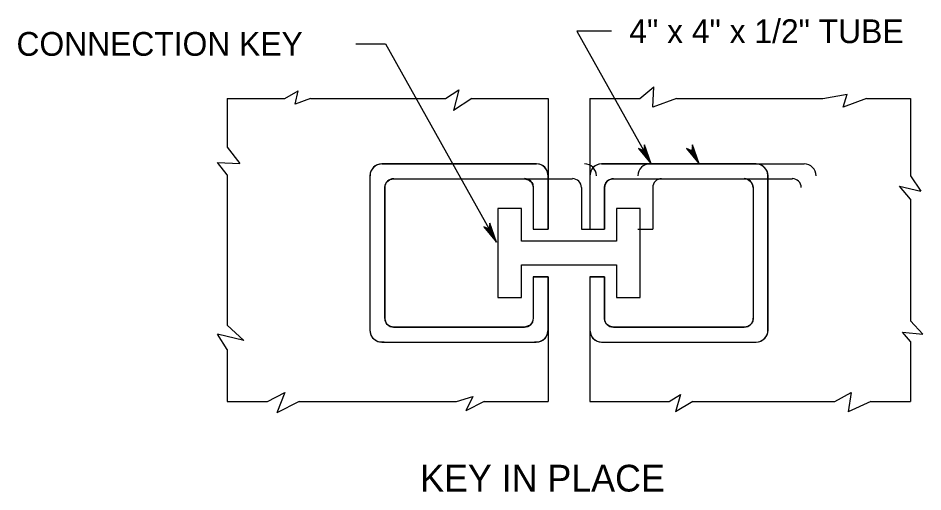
# Model space of a CAD drawing. Extents: x 499883 to 500983, y 499104 to 499764.
# Drawn here: x 500414.9 to 500567.1, y 499416 to 499495.7 of the extents above; entities that cross this region are included whole.
import ezdxf

# ---------------------------------------------------------------- set-up
doc = ezdxf.new("R2010")
doc.units = 0
doc.layers.add('5', color=7, linetype='Continuous')
doc.layers.add('60', color=7, linetype='Continuous')

msp = doc.modelspace()

# ---------------------------------------------------------------- linework, layer by layer
at = {"layer": '5'}
for p, q in [((500486.79, 499482.21), (500489.03, 499483.65)), ((500489.03, 499483.65), (500488.17, 499480.21)), ((500519.47, 499482.21), (500521.87, 499484.17)), ((500521.7, 499480.73), (500521.87, 499484.17)), ((500450.11, 499482.21), (500459.79, 499482.21)), ((500450.11, 499482.21), (500450.11, 499474.02)), ((500459.79, 499482.21), (500462.03, 499483.48)), ((500461.51, 499481.24), (500462.03, 499483.48)), ((500464.09, 499482.21), (500461.51, 499481.24)), ((500464.09, 499482.21), (500486.79, 499482.21)), ((500491.26, 499482.21), (500488.17, 499480.21)), ((500491.26, 499482.21), (500504.07, 499482.21)), ((500504.07, 499482.21), (500504.07, 499460.23)), ((500511.07, 499482.21), (500511.07, 499460.23)), ((500511.07, 499482.21), (500519.47, 499482.21)), ((500525.66, 499482.21), (500521.7, 499480.73)), ((500525.66, 499482.21), (500550.25, 499482.21)), ((500550.25, 499482.21), (500554.38, 499482.96)), ((500553.69, 499480.73), (500554.38, 499482.96)), ((500557.64, 499482.21), (500553.69, 499480.73)), ((500557.64, 499482.21), (500565.03, 499482.21)), ((500565.03, 499482.21), (500565.03, 499469.21)), ((500450.11, 499474.02), (500452.22, 499471.27)), ((500450.11, 499469.38), (500448.44, 499471.44)), ((500448.44, 499471.44), (500452.22, 499471.27)), ((500476.11, 499471.22), (500502.09, 499471.22)), ((500513.07, 499471.22), (500539.02, 499471.22)), ((500521.16, 499471.22), (500547.12, 499471.22)), ((500450.11, 499469.38), (500450.11, 499444.1)), ((500474.1, 499469.21), (500474.1, 499443.23)), ((500478.1, 499468.72), (500500.09, 499468.72)), ((500486.19, 499468.72), (500508.18, 499468.72)), ((500515.02, 499468.72), (500537.06, 499468.72)), ((500523.11, 499468.72), (500545.15, 499468.72)), ((500541.04, 499469.21), (500541.04, 499443.24)), ((500565.03, 499469.21), (500566.76, 499466.63)), ((500476.59, 499467.22), (500476.59, 499445.24)), ((500501.57, 499467.23), (500501.57, 499460.23)), ((500509.67, 499467.23), (500509.67, 499460.23)), ((500513.57, 499467.22), (500513.57, 499460.23)), ((500521.66, 499467.22), (500521.66, 499460.23)), ((500538.55, 499467.23), (500538.55, 499445.26)), ((500565.03, 499465.25), (500563.15, 499467.49)), ((500563.15, 499467.49), (500566.76, 499466.63)), ((500565.03, 499465.25), (500565.03, 499444.79)), ((500501.57, 499460.23), (500504.07, 499460.23)), ((500509.67, 499460.23), (500512.17, 499460.23)), ((500511.07, 499460.23), (500513.57, 499460.23)), ((500519.16, 499460.23), (500521.66, 499460.23)), ((500501.57, 499452.23), (500504.07, 499452.23)), ((500501.57, 499452.23), (500501.57, 499445.23)), ((500504.07, 499452.23), (500504.07, 499443.27)), ((500511.07, 499452.23), (500513.57, 499452.23)), ((500511.07, 499452.23), (500511.07, 499431.25)), ((500513.57, 499452.23), (500513.57, 499445.26)), ((500450.11, 499444.1), (500452.91, 499441.52)), ((500565.03, 499444.79), (500567.1, 499442.55)), ((500450.11, 499439.97), (500448.44, 499442.55)), ((500452.91, 499441.52), (500448.44, 499442.55)), ((500478.08, 499443.74), (500500.08, 499443.74)), ((500504.07, 499443.27), (500504.07, 499431.25)), ((500515.04, 499443.74), (500537.06, 499443.74)), ((500565.03, 499441.35), (500563.66, 499442.89)), ((500563.66, 499442.89), (500567.1, 499442.55)), ((500476.07, 499441.24), (500502.08, 499441.24)), ((500513.07, 499441.24), (500539.05, 499441.24)), ((500565.03, 499441.35), (500565.03, 499431.25)), ((500450.11, 499439.97), (500450.11, 499431.25)), ((500456.87, 499431.25), (500459.79, 499432.75)), ((500459.79, 499432.75), (500458.42, 499429.31)), ((500488.68, 499431.25), (500491.43, 499432.06)), ((500491.43, 499432.06), (500490.23, 499429.65)), ((500524.45, 499431.25), (500526.35, 499432.4)), ((500526.35, 499432.4), (500525.49, 499429.48)), ((500552.31, 499431.25), (500555.06, 499432.75)), ((500555.06, 499432.75), (500554.55, 499429.48)), ((500450.11, 499431.25), (500456.87, 499431.25)), ((500462.2, 499431.25), (500458.42, 499429.31)), ((500462.2, 499431.25), (500488.68, 499431.25)), ((500493.33, 499431.25), (500490.23, 499429.65)), ((500493.33, 499431.25), (500504.07, 499431.25)), ((500511.07, 499431.25), (500524.45, 499431.25)), ((500528.41, 499431.25), (500525.49, 499429.48)), ((500528.41, 499431.25), (500552.31, 499431.25)), ((500558.33, 499431.25), (500554.55, 499429.48)), ((500558.33, 499431.25), (500565.03, 499431.25))]:
    msp.add_line(p, q, dxfattribs=at)
for points in [[(500514.72, 499493.53), (500508.87, 499493.53), (500521.39, 499471.22)], [(500471.71, 499491.4), (500476.7, 499491.4), (500495.39, 499458.03)], [(500521.39, 499471.22), (500520.27, 499474.4), (500520.15, 499473.42), (500519.26, 499473.82), (500521.39, 499471.22), (500521.27, 499471.41), (500520.28, 499474.3), (500520.17, 499473.37), (500519.37, 499473.72), (500521.21, 499471.51), (500521.17, 499471.61), (500520.3, 499474.08), (500520.18, 499473.35), (500519.5, 499473.65), (500521.14, 499471.66), (500521.07, 499471.74), (500520.32, 499473.91), (500520.2, 499473.33), (500519.63, 499473.53), (500520.91, 499472.02), (500520.82, 499472.19), (500520.33, 499473.72), (500520.22, 499473.31), (500519.77, 499473.43), (500520.82, 499472.22), (500520.74, 499472.38), (500520.34, 499473.52), (500520.25, 499473.21), (500519.93, 499473.31), (500520.65, 499472.52), (500520.59, 499472.67), (500520.36, 499473.36), (500520.27, 499473.18), (500520.02, 499473.26), (500520.53, 499472.74), (500520.4, 499473.2), (500520.32, 499473.08), (500520.11, 499473.2), (500520.46, 499472.84), (500520.38, 499473.14), (500520.35, 499472.98), (500520.23, 499473.08), (500520.38, 499473), (500520.36, 499473.07)], [(500529.48, 499471.22), (500528.36, 499474.4), (500528.24, 499473.42), (500527.36, 499473.82), (500529.48, 499471.22), (500529.37, 499471.41), (500528.37, 499474.3), (500528.27, 499473.37), (500527.46, 499473.72), (500529.3, 499471.51), (500529.26, 499471.61), (500528.4, 499474.08), (500528.27, 499473.35), (500527.59, 499473.65), (500529.23, 499471.66), (500529.17, 499471.74), (500528.42, 499473.91), (500528.29, 499473.33), (500527.72, 499473.53), (500529.01, 499472.02), (500528.92, 499472.19), (500528.43, 499473.72), (500528.32, 499473.31), (500527.87, 499473.43), (500528.92, 499472.22), (500528.84, 499472.38), (500528.43, 499473.52), (500528.34, 499473.21), (500528.02, 499473.31), (500528.75, 499472.52), (500528.68, 499472.67), (500528.45, 499473.36), (500528.37, 499473.18), (500528.12, 499473.26), (500528.62, 499472.74), (500528.49, 499473.2), (500528.41, 499473.08), (500528.2, 499473.2), (500528.55, 499472.84), (500528.47, 499473.14), (500528.44, 499472.98), (500528.32, 499473.08), (500528.47, 499473), (500528.45, 499473.07)], [(500495.39, 499458.03), (500494.28, 499461.22), (500494.15, 499460.24), (500493.27, 499460.63), (500495.39, 499458.03), (500495.28, 499458.22), (500494.29, 499461.11), (500494.18, 499460.18), (500493.38, 499460.54), (500495.21, 499458.32), (500495.17, 499458.42), (500494.31, 499460.89), (500494.19, 499460.16), (500493.5, 499460.46), (500495.15, 499458.47), (500495.08, 499458.55), (500494.33, 499460.72), (500494.2, 499460.15), (500493.63, 499460.34), (500494.92, 499458.83), (500494.83, 499459), (500494.34, 499460.53), (500494.23, 499460.12), (500493.78, 499460.25), (500494.83, 499459.03), (500494.75, 499459.19), (500494.35, 499460.33), (500494.26, 499460.02), (500493.94, 499460.12), (500494.66, 499459.33), (500494.59, 499459.49), (500494.36, 499460.17), (500494.28, 499459.99), (500494.03, 499460.08), (500494.54, 499459.55), (500494.4, 499460.01), (500494.33, 499459.89), (500494.12, 499460.01), (500494.46, 499459.65), (500494.38, 499459.95), (500494.36, 499459.79), (500494.23, 499459.89), (500494.39, 499459.81), (500494.36, 499459.88)]]:
    msp.add_lwpolyline(points, dxfattribs=at)
for centre, radius, start, end in [((500476.11, 499469.22), 2, 90, 180), ((500502.09, 499469.22), 2, 0, 90), ((500510.18, 499469.22), 2, 0, 90), ((500513.07, 499469.22), 2, 90, 180), ((500521.16, 499469.22), 2, 90, 180), ((500539.05, 499469.21), 2, 0, 90), ((500547.14, 499469.21), 2, 0, 90), ((500478.09, 499467.22), 1.5, 90, 180), ((500500.08, 499467.23), 1.5, 0, 90), ((500508.17, 499467.23), 1.5, 0, 90), ((500515.06, 499467.22), 1.5, 90, 180), ((500523.16, 499467.22), 1.5, 90, 180), ((500537.05, 499467.23), 1.5, 0, 90), ((500545.14, 499467.23), 1.5, 0, 90), ((500478.09, 499445.24), 1.5, 180, 270), ((500500.08, 499445.24), 1.5, 270, 0), ((500515.04, 499445.24), 1.5, 180, 270), ((500537.06, 499445.24), 1.5, 270, 0), ((500476.09, 499443.23), 2, 180, 270), ((500502.08, 499443.24), 2, 270, 0), ((500513.07, 499443.24), 2, 180, 270), ((500539.05, 499443.24), 2, 270, 0)]:
    msp.add_arc(centre, radius, start, end, dxfattribs=at)
at = {"layer": '60'}
for points in [[(500500.09, 499468.72), (500500.9, 499468.48), (500501.31, 499468.08), (500501.47, 499467.78), (500501.57, 499467.23), (500501.57, 499460.23), (500504.07, 499460.23), (500504.09, 499469.22), (500503.9, 499470.06), (500503.53, 499470.61), (500503.03, 499470.98), (500502.63, 499471.14), (500502.09, 499471.22), (500476.11, 499471.22), (500475.22, 499471.01), (500474.67, 499470.61), (500474.32, 499470.12), (500474.15, 499469.64), (500474.1, 499469.21), (500474.1, 499443.23), (500474.27, 499442.41), (500474.54, 499441.97), (500474.95, 499441.59), (500475.42, 499441.34), (500477.55, 499441.24), (500500.9, 499441.24), (500502.6, 499441.31), (500503.15, 499441.55), (500503.62, 499441.97), (500503.91, 499442.45), (500504.07, 499443.27), (500504.07, 499452.23), (500501.57, 499452.23), (500501.57, 499445.23), (500501.42, 499444.57), (500501.03, 499444.08), (500500.08, 499443.74), (500478.08, 499443.74), (500477.39, 499443.91), (500477.02, 499444.2), (500476.8, 499444.48), (500476.59, 499445.24), (500476.59, 499467.22), (500476.66, 499467.67), (500476.88, 499468.1), (500477.09, 499468.33), (500477.45, 499468.58), (500478.1, 499468.72)], [(500513.07, 499471.22), (500512.59, 499471.16), (500511.96, 499470.88), (500511.48, 499470.44), (500511.23, 499470.01), (500511.07, 499469.22), (500511.07, 499460.23), (500513.57, 499460.23), (500513.57, 499467.22), (500513.62, 499467.63), (500513.78, 499468.01), (500514.06, 499468.34), (500514.41, 499468.57), (500515.02, 499468.72), (500537.06, 499468.72), (500537.59, 499468.63), (500538.07, 499468.33), (500538.28, 499468.08), (500538.46, 499467.74), (500538.55, 499467.23), (500538.55, 499445.26), (500538.47, 499444.73), (500538.23, 499444.3), (500537.93, 499444.01), (500537.65, 499443.86), (500537.06, 499443.74), (500515.04, 499443.74), (500514.39, 499443.89), (500513.91, 499444.26), (500513.62, 499444.77), (500513.57, 499445.26), (500513.57, 499452.23), (500511.07, 499452.23), (500511.07, 499443.24), (500511.3, 499442.31), (500511.55, 499441.94), (500511.97, 499441.57), (500512.3, 499441.39), (500513.07, 499441.24), (500539.05, 499441.24), (500539.67, 499441.34), (500540.19, 499441.6), (500540.55, 499441.93), (500540.83, 499442.34), (500541, 499442.82), (500541.04, 499443.24), (500541.04, 499469.21), (500540.97, 499469.74), (500540.71, 499470.31), (500540.18, 499470.85), (500539.8, 499471.06), (500539.37, 499471.18), (500539.02, 499471.22)], [(500495.58, 499463.72), (500495.58, 499448.73), (500499.58, 499448.73), (500499.58, 499454.23), (500515.56, 499454.23), (500515.56, 499448.73), (500519.56, 499448.73), (500519.56, 499463.72), (500515.56, 499463.72), (500515.56, 499458.23), (500499.58, 499458.23), (500499.58, 499463.72)]]:
    msp.add_lwpolyline(points, close=True, dxfattribs=at)

# ---------------------------------------------------------------- texts
at = {"layer": '5'}
for s, height, p in [('4" x 4" x 1/2" TUBE', 4, (500517.72, 499491.53)), ('CONNECTION KEY', 4, (500414.65, 499489.4)), ('KEY IN PLACE', 4.5, (500482.55, 499416.08))]:
    msp.add_text(s, height=height, dxfattribs=at).set_placement(p)

doc.saveas('drawing.dxf')
